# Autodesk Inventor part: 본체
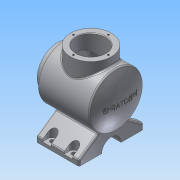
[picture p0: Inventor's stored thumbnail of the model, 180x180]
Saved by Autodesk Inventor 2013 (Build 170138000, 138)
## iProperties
Created: 2017-04
Part Number: 본체
Material: 알루미늄 6061
Document SubType Name: Modeling
Designer: Administrator
Density: 2.71 g/cm^3
Mass: 1692.14 g
Surface Area: 1071.71 cm^2
Volume: 624.405 cm^3
Author: Administrator
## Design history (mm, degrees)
sketch "스케치1"
  geometry: L1 (0, 0)-(120, 0); L2 (0, 0)-(0, 38); L3 (0, 38)-(12, 38); L4 (12, 38)-(12, 50); L5 (12, 50)-(108.336, 50); L6 (0, 27)-(22, 27); L7 (22, 27)-(22, 40); L8 (22, 40)-(101.916, 40); A1 r 113 centre (7, 0) between (120, 0) and (108.336, 50); A2 r 103 centre (7, 0) between (110, 0) and (101.916, 40)
  constraints: 16 end point, 4 parallel, 4 point on circle, 3 perpendicular, 3 point on line, 2 centre point, 1 horizontal
  dimensions: "d0" = 120 distance of L1.start L1.end; "d1" = 113 radius of A1; "d2" = 100 diameter of L5 L1; "d3" = 76 diameter of L3 L1; "d4" = 12 distance of L2.end L3.end; "d5" = 10 radial gap between concentric circles of A1 A2; "d6" = 54 diameter of L6 L1; "d7" = 80 diameter of L8 L1; "d8" = 22 distance of L6.start L6.end
revolve "회전1" sketch "스케치1" stored, may be unused: angle "d9" = 90 deg
node "작업 평면1"
sketch "스케치2"
  geometry: L1 (12, 50)-(108.336, 50) reference; L2 (12, -50)-(12, 50) reference; C1 r 38 at (62, 0); 1 further point
  constraints: 1 centre point, 1 horizontal alignment
  dimensions: "d11" = 76 diameter of C1; "d14" = 50 distance from line of C1.centre L2
extrude "돌출1" join sketch "스케치2" stored distance "d15" = 10; taper "d16" = 0 deg
sketch "스케치3"
  geometry: C1 r 38 at (0, 0) reference; C2 r 27 at (0, 0); 1 further point
  constraints: 1 centre point, 1 coincident
  dimensions: "d17" = 54 diameter of C2
extrude "돌출2" cut sketch "스케치3" distance "d19" = 40; taper "d20" = 0 deg
node "작업 평면4"
  node "작업 평면3"
sketch "스케치4"
  geometry: L1 (-18.364, -42.846)-(-60, -72); L2 (-60, -72)-(-60, -82); L3 (-60, -82)-(60, -82); L4 (60, -82)-(60, -72); L5 (60, -72)-(18.364, -42.846); L6 (-18.364, -42.846)-(18.364, -42.846); C1 r 50 at (0, 0) reference; C2 r 27 at (0, 0) reference; 2 further points
  constraints: 12 end point, 3 perpendicular, 1 midpoint, 1 parallel, 1 vertical, 1 vertical alignment
  dimensions: "d23" = 10 distance of L1.end L2.end; "d25" = 120 distance of L2.end L3.end; "d26" = 55 deg angle of L2 L1; "d27" = 55 deg angle of L4 L5; "d28" = 82 distance from line of L3 point (0, 0)
extrude "돌출3" join sketch "스케치4" distance "d29" = 80; taper "d30" = 0 deg
node "작업 평면5"
sketch "스케치5"
  geometry: L1 (100, 21.584)-(20, 21.584) reference; L2 (100, 60)-(100, 21.584) reference; L3 (20, 60)-(100, 60) reference; L4 (20, 60)-(20, 21.584) reference; L5 (32, 60)-(32, 50); L6 (48, 60)-(48, 50); L7 (72, 60)-(72, 50); L8 (88, 60)-(88, 50); A1 r 8 centre (40, 50) between (32, 50) and (48, 50); A2 r 8 centre (80, 50) between (72, 50) and (88, 50); 1 further point
  constraints: 8 end point, 4 point on circle, 4 point on line, 4 tangent, 3 parallel, 2 centre point, 2 perpendicular, 1 equal radius
  dimensions: "d32" = 8 radius of A1; "d33" = 20 distance from line of L4 A1.centre; "d34" = 10 distance from line of A1.centre L3; "d35" = 20 distance from line of L2 A2.centre
extrude "돌출4" cut sketch "스케치5" distance "d36" = 21; taper "d37" = 0 deg
node "작업 평면6"
node "작업 평면7"
sketch "스케치6"
  geometry: L1 (72, 50)-(72, 60) reference; L2 (88, 60)-(88, 50) reference; L3 (72, 60)-(88, 60) reference; L4 (32, -50)-(32, -60) reference; L5 (48, -60)-(32, -60) reference; L6 (48, -60)-(48, -50) reference; L7 (72, -50)-(72, -60) reference; L8 (88, -60)-(72, -60) reference; L9 (88, -60)-(88, -50) reference; C1 r 4 at (40, 50); C2 r 4 at (80, 50); C3 r 4 at (40, -50); C4 r 4 at (80, -50); A1 r 8 centre (40, 50) between (32, 50) and (48, 50) reference; A2 r 8 centre (80, 50) between (72, 50) and (88, 50) reference; A3 r 8 centre (40, -50) between (48, -50) and (32, -50) reference; A4 r 8 centre (80, -50) between (88, -50) and (72, -50) reference; 1 further point
  constraints: 4 centre point, 4 coincident, 3 equal radius
  dimensions: "d38" = 8 diameter of C1
extrude "돌출5" cut sketch "스케치6" distance "d40" = 20; taper "d41" = 0 deg
sketch "스케치7"
  geometry: L1 (-82, -60)-(-82, 60) reference; C1 r 18 at (-82, 0)
  constraints: 1 centre point, 1 midpoint
  dimensions: "d42" = 36 diameter of C1
extrude "돌출6" cut sketch "스케치7" distance "d44" = 100; taper "d45" = 0 deg
sketch "스케치8"
  geometry: C1 r 38 at (0, 0) reference; C2 r 27 at (0, 0) reference; A1 r 32.5 centre (0, 0) between (32.5, 0) and (0, 32.5); 2 further points
  constraints: 4 point on circle, 2 horizontal alignment, 2 vertical alignment, 1 centre point, 1 coincident
  dimensions: "d46" = 65 diameter of A1
hole "구멍1" sketch "스케치8" at (32.5, 0), (0, 32.5), (-32.5, 0), (0, -32.5) diameter "d49" = 3.242; stored, may be unused: countersink angle "d53" = 90 deg, drill point angle "d55" = 118 deg; dims "d50" = 8, "d51" = 4, "d52" = 2, "d54" = 10
sketch "스케치9"
  geometry: C1 r 27 at (0, 0) reference; C2 r 38 at (0, 0) reference; A1 r 32.5 centre (0, 0) between (0, 32.5) and (-32.5, 0); 3 further points
  constraints: 4 point on circle, 2 horizontal alignment, 2 vertical alignment, 1 centre point, 1 coincident
  dimensions: "d56" = 65 diameter of A1
hole "구멍2" sketch "스케치9" at (0, 32.5), (-32.5, 0), (0, -32.5), (32.5, 0) diameter "d58" = 3.242; stored, may be unused: countersink angle "d62" = 90 deg, drill point angle "d64" = 118 deg; dims "d59" = 8, "d60" = 4, "d61" = 2, "d63" = 10
fillet "모깎기1" dims "d65" = 3
chamfer "모따기1" distance "d66" = 1; stored, may be unused: second distance "d67" = 2, angle "d68" = 45 deg
fillet "모깎기2" dims "d69" = 3
node "작업 평면8"
sketch "스케치10"
  geometry: L1 (60, -82)-(60, -73.562) reference; L2 (-38, 65)-(38, 65) reference; 3 further points
  constraints: 1 coincident, 1 midpoint, 1 vertical alignment, 1 other
feature "엠보싱1" sketch "스케치10" dims "d0" = 120, "d1" = 113, "d2" = 100, "d3" = 76, "d4" = 12, "d5" = 10, "d6" = 54, "d7" = 80, "d8" = 22, "d72" = 0.5, "d73" = 0
fillet "모깎기3" dims "d74" = 3
node "솔리드1"
mirror "대칭1"
node "작업 평면2"
node "투영된 루프1"
node "투영된 루프2"
node "투영된 루프3"
node "투영된 루프4"
node "절단 모서리 투영1"
other parameters: "d10" = 65, "d21" = 6, "d22" = -8, "d31" = -55, "d70" = 132
